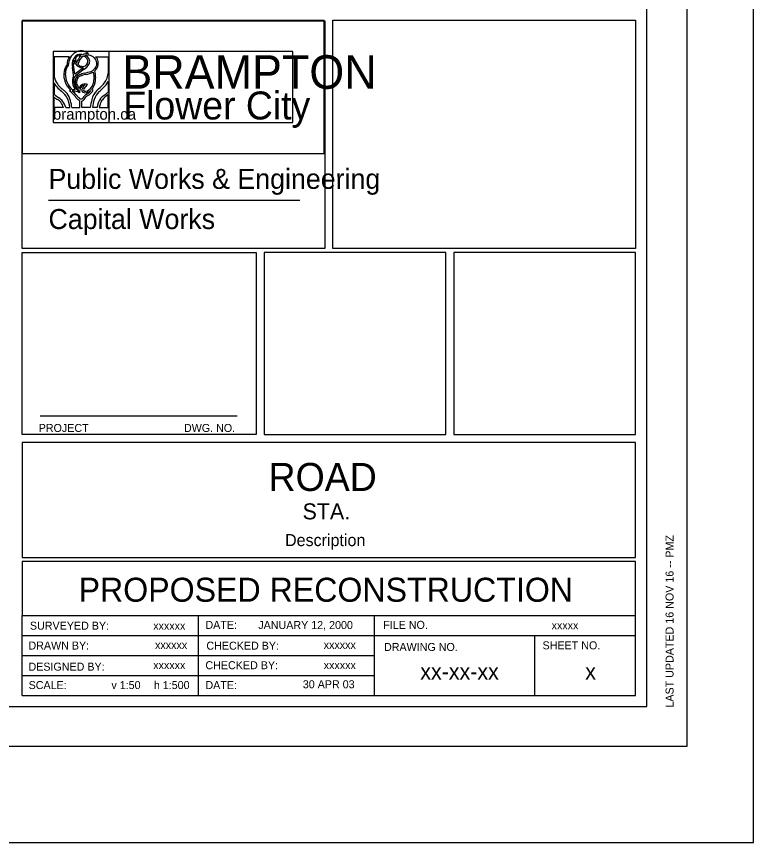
# Model space of a CAD drawing. Extents: x 595568 to 603709, y 4837996 to 4846716.
# Drawn here: x 603285 to 603377, y 4846340.6 to 4846443.8 of the extents above; entities that cross this region are included whole.
import ezdxf

# ---------------------------------------------------------------- set-up
doc = ezdxf.new("R2010")
doc.units = 0
for name, color, linetype in [('-PRINT FULLSIZE', 7, 'Continuous'), ('-PRINT HALFSIZE', 7, 'Continuous'), ('ENG_BORDER', 7, 'Continuous'), ('ENG_LOGO', 7, 'Continuous'), ('ENG_TITLEBLOCK', 7, 'Continuous'), ('ENG_TX_BORDER', 7, 'Continuous'), ('ENG_TX_LOGO', 7, 'Continuous'), ('ENG_TX_TITLE-DESC', 7, 'Continuous'), ('ENG_TX_TITLEBLOCK', 7, 'Continuous'), ('ENG_WK_MISC-2', 7, 'Continuous')]:
    doc.layers.add(name, color=color, linetype=linetype)

msp = doc.modelspace()

# ---------------------------------------------------------------- linework, layer by layer
at = {"layer": '-PRINT FULLSIZE'}
msp.add_lwpolyline([(602930, 4846340.65), (603377.03, 4846340.65), (603377.03, 4846645.65), (602930, 4846645.65)], close=True, dxfattribs=at)
at = {"layer": '-PRINT HALFSIZE'}
msp.add_lwpolyline([(602959.8, 4846631.64), (603368.72, 4846631.64), (603368.72, 4846352.64), (602959.8, 4846352.64)], close=True, dxfattribs=at)
at = {"layer": 'ENG_BORDER'}
msp.add_lwpolyline([(602975.52, 4846357.64), (603363.72, 4846357.64), (603363.72, 4846626.64), (602975.52, 4846626.64)], close=True, dxfattribs=at)
at = {"layer": 'ENG_LOGO'}
for p, q in [((603291.59, 4846438.78), (603289.69, 4846438.78)), ((603289.69, 4846438.78), (603289.69, 4846436.55)), ((603294.87, 4846438.78), (603296.45, 4846438.78)), ((603296.45, 4846438.78), (603296.45, 4846436.69)), ((603292.28, 4846436.61), (603292.13, 4846437.81)), ((603292.1, 4846436.53), (603291.98, 4846437.48)), ((603293.36, 4846437.42), (603292.28, 4846436.61)), ((603293.45, 4846437.25), (603292.37, 4846436.44)), ((603296.45, 4846435.73), (603296.45, 4846434.4)), ((603289.69, 4846435.53), (603289.69, 4846434.15)), ((603291.94, 4846434.73), (603292.31, 4846434.73)), ((603292.75, 4846434.49), (603292.75, 4846434.59)), ((603293.93, 4846434.23), (603294.32, 4846434.6)), ((603289.69, 4846432.45), (603289.69, 4846433.78)), ((603296.45, 4846432.45), (603296.45, 4846434.03)), ((603292.9, 4846432.45), (603292.9, 4846433.31)), ((603293.16, 4846432.45), (603293.16, 4846433.27)), ((603290.87, 4846432.45), (603289.69, 4846432.45)), ((603291.14, 4846432.45), (603291.65, 4846432.45)), ((603291.91, 4846432.45), (603292.9, 4846432.45)), ((603294.21, 4846432.45), (603293.16, 4846432.45)), ((603295.09, 4846432.45), (603294.48, 4846432.45)), ((603295.34, 4846432.45), (603296.45, 4846432.45))]:
    msp.add_line(p, q, dxfattribs=at)
for centre, major_axis, start_param, end_param in [((603292.63, 4846437.83), (0, 1.57), 0.915828, 1.568717), ((603293.06, 4846437.61), (0, 1.92), 5.678233, 7.807497), ((603293.02, 4846437.83), (0, -1.29), 3.318986, 4.976585), ((603292.72, 4846438.47), (0, 0.423), 0.666047, 1.576027), ((603293.98, 4846437.43), (0, 1.86), 0.628774, 1.255965), ((603292.93, 4846438), (0, 0.951), 6.118882, 6.855525), ((603294.04, 4846437.35), (0, 1.73), 0.484278, 1.276713), ((603292.96, 4846438.11), (0, 0.995), 5.937042, 6.443816), ((603293.86, 4846437.3), (0, 1.9), 6.209925, 6.677582), ((603293.17, 4846437.98), (0, 0.932), 5.514665, 6.02559), ((603293.87, 4846437.57), (0, 1.44), 6.104016, 6.552384), ((603293.36, 4846438.01), (0, 0.978), 5.100192, 6.058655), ((603293.74, 4846436.93), (0, 2.1), 5.705811, 6.088794), ((603294.28, 4846437.96), (0, 0.893), 4.747453, 5.681752), ((603294.51, 4846438.07), (0, 0.833), 4.858966, 5.733736), ((603292.24, 4846436.68), (0, 1.59), 0.764321, 1.571722), ((603292.2, 4846436.72), (0, 1.32), 0.74139, 1.563754), ((603292.99, 4846437.92), (0, 1.03), 1.119551, 1.674398), ((603293.23, 4846438.42), (0, -1.22), 4.758696, 4.974719), ((603292.61, 4846438.23), (0, -0.454), 4.989814, 5.515803), ((603292.8, 4846438.39), (0, 0.526), 1.423327, 2.376918), ((603293.28, 4846438.93), (0, -1.51), 5.455385, 6.346676), ((603293.21, 4846438.61), (0, -1), 5.558935, 6.198642), ((603293.28, 4846438.47), (0, -0.881), 6.098575, 6.969537), ((603292.71, 4846439.02), (0, -1.97), 0.460861, 0.945922), ((603293.47, 4846438.2), (0, 0.536), 4.934552, 5.720905), ((603293.34, 4846438.27), (0, -0.677), 0.785512, 1.640949), ((603293.5, 4846438.24), (0, 0.761), 4.195874, 4.894963), ((603294.45, 4846437.92), (0, 0.697), 3.823835, 4.807307), ((603293.68, 4846438.04), (0, -1.82), 1.316711, 1.656268), ((603292.46, 4846436.54), (0, 1.86), 1.493845, 2.002346), ((603293.12, 4846436.69), (0, 2.42), 1.555738, 2.522651), ((603291.88, 4846437.46), (0, -0.13), 1.717889, 1.834992), ((603294.4, 4846431.68), (0, 5.19), 0.207106, 0.364997), ((603292.27, 4846445.86), (0, -9.21), 0.161819, 0.267812), ((603292.57, 4846443.68), (0, -7.22), 0.177455, 0.344982), ((603293.88, 4846438.4), (0, -1.51), 0.344201, 0.831804), ((603292.75, 4846436.21), (0, 2.33), 4.273394, 5.005808), ((603293.97, 4846438.32), (0, -1.6), 0.654188, 1.084874), ((603292.14, 4846436.18), (0, -3.28), 1.565289, 1.83996), ((603294.67, 4846437.01), (0, -2.14), 0.712478, 1.421371), ((603291.18, 4846436.68), (0, -1.79), 4.785712, 5.370532), ((603292.82, 4846438.2), (0, -4.27), 5.369755, 5.566262), ((603292.88, 4846436.56), (0, -2.33), 5.06368, 5.674398), ((603293.36, 4846435.78), (0, 1.64), 1.184297, 2.265825), ((603291.89, 4846436.5), (0, 0.259), 4.32589, 4.859481), ((603292.7, 4846435.9), (0, 0.673), 0.63706, 1.540523), ((603293.63, 4846435.88), (0, -1.78), 4.68622, 4.981796), ((603293.46, 4846435.69), (0, 1.35), 1.258524, 1.853874), ((603293.08, 4846435.61), (0, 0.963), 0.28455, 1.028854), ((603293.21, 4846435.63), (0, 0.845), 1.326911, 2.090694), ((603293.04, 4846435.75), (0, 0.62), 0.179588, 1.425103), ((603294.11, 4846432.81), (0, 3.81), 0.147367, 0.372097), ((603293.29, 4846436.07), (0, -1.9), 0.78097, 1.623824), ((603294.19, 4846437.42), (0, -3.18), 0.682687, 1.010528), ((603291.63, 4846437.05), (0, -2.78), 5.292666, 5.605077), ((603292.46, 4846437.85), (0, -4.03), 5.537119, 5.75381), ((603335.94, 4846507.05), (0, -90.24), 5.63745, 5.644913), ((603290.29, 4846433.17), (0, 1.6), 5.416876, 5.78378), ((603292.04, 4846433.78), (0, 0.938), 0.365522, 0.597805), ((603293.61, 4846435.94), (0, -1.78), 5.019488, 5.665896), ((603293.68, 4846435.77), (0, -1.63), 4.995413, 5.526463), ((603293.54, 4846435.71), (0, -1.23), 5.131028, 5.477302), ((603293.54, 4846434.39), (0, 1.01), 5.87892, 7.368381), ((603293.56, 4846434.43), (0, -0.828), 3.173377, 4.865507), ((603293.39, 4846434.62), (0, 0.273), 1.287529, 2.899642), ((603293.87, 4846434.49), (0, 0.861), 0.477744, 1.324571), ((603293.54, 4846434.69), (0, 0.193), 0.693494, 2.795441), ((603294.59, 4846433.87), (0, 1.68), 0.532188, 0.957727), ((603292.97, 4846437.68), (0, -3.48), 0.25264, 0.48256), ((603293.29, 4846436.12), (0, -1.71), 0.401305, 1.020747), ((603292.2, 4846437.04), (0, -3.74), 0.664019, 0.865631), ((603294.22, 4846433.96), (0, 0.792), 5.695616, 5.978543), ((603296.02, 4846433.01), (0, 1.97), 0.6523, 1.336939), ((603276.65, 4846462.29), (0, -35.35), 0.669806, 0.705808), ((603286.42, 4846449.27), (0, -18.23), 0.619451, 0.667551), ((603292.96, 4846439.2), (0, -6.39), 5.623762, 5.757196), ((603292.15, 4846438.13), (0, -5.26), 5.687848, 5.809574), ((603288.7, 4846430.56), (0, 3.64), 5.540505, 5.738863), ((603289.41, 4846432.14), (0, 2.75), 5.320654, 5.659535), ((603289.53, 4846432.31), (0, 2.53), 4.76812, 5.296774), ((603289.87, 4846432.61), (0, 2.34), 5.018027, 5.462353), ((603290.48, 4846431.99), (0, 2.89), 5.439641, 5.800947), ((603292.06, 4846432.33), (0, 2.2), 5.823202, 6.334077), ((603289.95, 4846430.9), (0, 4.35), 5.482733, 5.697338), ((603284.51, 4846424.95), (0, 12.9), 5.441321, 5.480214), ((603293.48, 4846434.8), (0, -1.39), 5.382989, 5.704264), ((603293.04, 4846434.03), (0, -0.731), 5.423199, 6.055208), ((603293.07, 4846433.96), (0, -0.427), 5.581796, 6.941571), ((603292.89, 4846434.25), (0, -1.03), 0.32402, 1.048968), ((603291.65, 4846435.42), (0, -2.66), 0.828888, 0.938456), ((603293.58, 4846435.08), (0, -0.775), 5.896411, 6.466099), ((603293.79, 4846433.66), (0, 0.445), 0.214109, 1.153309), ((603293.58, 4846435.9), (0, -1.39), 6.206413, 6.519617), ((603294.07, 4846433.25), (0, 0.72), 0.422403, 0.821661), ((603293.06, 4846435.97), (0, -2.02), 0.390063, 0.537232), ((603292.96, 4846436.29), (0, -2.6), 0.408149, 0.566756), ((603296.65, 4846432.45), (0, 2.56), 0.690534, 1.157714), ((603296.53, 4846432.37), (0, 1.73), 0.824174, 1.519908), ((603296.57, 4846432.42), (0, 1.73), 0.445246, 0.869293), ((603297.42, 4846431.43), (0, 2.85), 0.417687, 0.818457), ((603291.25, 4846442.66), (0, -10.34), 0.573803, 0.643743), ((603289.49, 4846431.89), (0, 1.75), 5.497917, 5.817483), ((603289.43, 4846431.87), (0, 1.81), 5.039091, 5.480629), ((603289.47, 4846431.82), (0, 2.1), 5.021624, 5.458474), ((603289.15, 4846432.12), (0, 3.31), 4.811691, 5.079969), ((603298.33, 4846431.78), (0, 4.97), 1.223572, 1.434629), ((603301.37, 4846430.99), (0, 8.37), 1.268607, 1.395258), ((603297.1, 4846432.09), (0, 2.14), 0.923116, 1.39853)]:
    msp.add_ellipse(centre, major_axis=major_axis, ratio=0.837209, start_param=start_param, end_param=end_param, dxfattribs=at)
at = {"layer": 'ENG_TITLEBLOCK'}
for p, q in [((603288.99, 4846420.87), (603320.37, 4846420.87)), ((603287.95, 4846393.94), (603312.57, 4846393.94)), ((603285.69, 4846359.01), (603285.69, 4846369.01)), ((603285.69, 4846369.01), (603362.31, 4846369.01)), ((603307.71, 4846359.01), (603307.71, 4846369.01)), ((603329.71, 4846359.01), (603329.71, 4846369.01)), ((603362.31, 4846359.01), (603362.31, 4846369.01)), ((603285.69, 4846366.51), (603362.31, 4846366.51)), ((603349.71, 4846359.01), (603349.71, 4846366.51)), ((603285.69, 4846364.01), (603329.71, 4846364.01)), ((603285.69, 4846361.51), (603329.71, 4846361.51)), ((603285.69, 4846359.01), (603362.31, 4846359.01))]:
    msp.add_line(p, q, dxfattribs=at)
for points in [[(603285.69, 4846443.3), (603323.5, 4846443.3), (603323.5, 4846414.83), (603285.69, 4846414.83)], [(603324.5, 4846443.36), (603362.31, 4846443.36), (603362.31, 4846414.83), (603324.5, 4846414.83)], [(603314.91, 4846391.63), (603285.69, 4846391.63), (603285.69, 4846414.33), (603314.91, 4846414.33)], [(603315.91, 4846391.63), (603338.61, 4846391.63), (603338.61, 4846414.33), (603315.91, 4846414.33)], [(603339.61, 4846391.63), (603362.31, 4846391.63), (603362.31, 4846414.33), (603339.61, 4846414.33)], [(603285.69, 4846376.23), (603362.31, 4846376.23), (603362.31, 4846390.63), (603285.69, 4846390.63)], [(603285.69, 4846369.01), (603362.31, 4846369.01), (603362.31, 4846375.73), (603285.69, 4846375.73)]]:
    msp.add_lwpolyline(points, close=True, dxfattribs=at)
at = {"layer": 'ENG_WK_MISC-2'}
for points in [[(603285.69, 4846426.71), (603323.4, 4846426.71), (603323.4, 4846443.33), (603285.69, 4846443.33)], [(603289.58, 4846430.6), (603319.51, 4846430.6), (603319.51, 4846439.45), (603289.58, 4846439.45)], [(603289.58, 4846430.6), (603296.56, 4846430.6), (603296.56, 4846439.45), (603289.58, 4846439.45)]]:
    msp.add_lwpolyline(points, close=True, dxfattribs=at)

# ---------------------------------------------------------------- texts
at = {"layer": 'ENG_TX_BORDER'}
for s, height, rotation, p in [('ROAD', 3.5, 360, (603316.47, 4846384.56)), ('STA.', 2, 360, (603320.72, 4846381.01)), ('Description', 1.5, 360, (603318.53, 4846377.67)), ('LAST UPDATED 16 NOV 16 -- PMZ', 1, 90, (603367.05, 4846357.5)), ('xx-xx-xx', 2, 360, (603335.42, 4846361)), ('x', 2, 360, (603356.02, 4846361))]:
    msp.add_text(s, height=height, rotation=rotation, dxfattribs=at).set_placement(p)
at = {"layer": 'ENG_TX_LOGO'}
msp.add_text('brampton.ca', height=1.3968, rotation=0.002, dxfattribs=at).set_placement((603289.54, 4846430.94))
at = {"layer": 'ENG_TX_TITLE-DESC'}
msp.add_text('PROPOSED RECONSTRUCTION', height=3, rotation=360, dxfattribs=at).set_placement((603292.75, 4846370.72))
at = {"layer": 'ENG_TX_TITLEBLOCK'}
for s, height, rotation, p in [('BRAMPTON', 4.191, 0.0021, (603298.21, 4846434.8)), ('Flower City', 3.4921, 0.0021, (603298.33, 4846430.97)), ('Public Works & Engineering', 2.5, 0.0021, (603288.99, 4846422.3)), ('Capital Works', 2.5, 0.0021, (603288.99, 4846417.28)), ('PROJECT', 1, 360, (603287.77, 4846391.93)), ('DWG. NO.', 1, 360, (603305.91, 4846391.93)), ('SURVEYED BY:            ', 1, 360, (603286.67, 4846367.23)), ('xxxxxx', 1, 360, (603302.07, 4846367.22)), ('DATE:', 1, 360, (603308.59, 4846367.33)), ('JANUARY 12, 2000', 1, 360, (603315.19, 4846367.31)), ('FILE NO.', 1, 360, (603330.79, 4846367.33)), ('xxxxx', 1, 360, (603351.82, 4846367.27)), ('DRAWN BY:              ', 1, 360, (603286.49, 4846364.75)), ('xxxxxx', 1, 360, (603302.3, 4846364.82)), ('CHECKED BY:', 1, 360, (603308.71, 4846364.73)), ('xxxxxx', 1, 360, (603323.36, 4846364.83)), ('DRAWING NO.', 1, 360, (603330.89, 4846364.57)), ('SHEET NO.', 1, 360, (603350.69, 4846364.77)), ('DESIGNED BY:', 1, 360, (603286.49, 4846362.11)), ('xxxxxx', 1, 360, (603302.07, 4846362.3)), ('CHECKED BY:', 1, 360, (603308.59, 4846362.29)), ('xxxxxx', 1, 360, (603323.36, 4846362.3)), ('SCALE:', 1, 360, (603286.51, 4846359.81)), ('v 1:50', 1, 360, (603296.85, 4846359.81)), ('h 1:500', 1, 360, (603302.15, 4846359.81)), ('DATE:', 1, 360, (603308.59, 4846359.81)), ('30 APR 03', 1, 360, (603320.75, 4846359.91))]:
    msp.add_text(s, height=height, rotation=rotation, dxfattribs=at).set_placement(p)

doc.saveas('drawing.dxf')
